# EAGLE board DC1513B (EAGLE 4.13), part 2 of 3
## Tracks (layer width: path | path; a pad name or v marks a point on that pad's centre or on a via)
3V  (via drill 0.3, 0.38)
  Top 0.152: v41.28,31.12 U9.G13
  Top 0.203: R29.2 81.92,12 v81.92,12.95
  Top 0.254: SJ2.1 U6.9 | SJ2.1 | U6.10 SJ1.1 79.12,64.14 | SJ2.1 79.63,64.13 79.63,64.14 | 79.38,65.53 79.5,65.53
  Top 0.305: 79.63,64.14 79.63,65.41 79.5,65.53 | 79.12,64.14 79.12,65.15 79.5,65.53 | 79.5,65.53 C15.1 | v41.91,27.31 U9.D14
  Top 0.406: v41.91,33.66 U9.J14
  Top 0.61: 79.38,65.53 79.38,65.41 78.99,65.02 77.47,65.02 77.09,64.64 v76.96,64.64 69.85,64.64 68.58,65.91 TP5.1 | U9.F13 v41.28,31.12 U9.G13
  L2-GND 0.203: 42.29,69.47 42.28,69.47 J4.2
  L2-GND 0.305: J3.6 35.59,65.31 36.07,65.79 36.07,69.98 36.45,70.36 42.29,70.36 | 42.28,69.34 42.29,69.34 42.29,69.47 42.29,70.36 | 42.29,70.36 54.99,70.36 56.13,69.22 66.04,69.22 TP5.1
  Bottom 0.203: v41.91,27.31 42.16,27.31 42.29,27.43 42.8,27.43 R28.2 | 42.67,37.08 R27.2 | R34.1 40.76,35.55 40.77,35.56
  Bottom 0.254: R36.1 41.72,70.36 41.78,70.36 42.28,69.87 J4.2 | R39.1 41.1,29.48 41.1,30.18 | v41.28,31.12 41.28,30.35 41.1,30.18 | R33.1 40.27,30.18 41.1,30.18
  Bottom 0.305: 81.15,13.59 v81.92,12.95 | J3.6 34.67,65.28 32.69,65.28 J3.5 | v41.91,27.31 41.28,27.94 41.28,28.96 41.02,29.21 41.02,29.46 R39.1
  Bottom 0.406: 81.15,13.59 79.88,13.59 78.74,14.73 78.74,44.96 77.72,45.97 77.72,58.55 76.96,59.31 v76.96,64.64 | L1.2 42.68,37.08 42.67,37.08 42.67,35.56 | 42.67,35.56 42.67,34.42 v41.91,33.66 41.4,33.15 41.4,32 41.28,31.88 v41.28,31.12 C20.1 | 42.67,35.56 40.77,35.56
  Bottom 0.508: L1.2 43.32,38.47 42.8,38.99 42.8,39.12 | 42.8,39.12 42.8,40.51 | 42.8,39.12 R32.2
  Bottom 0.61: TP5.1 68.58,69.03 C19.1 68.58,68.33 68.58,55.5 67.56,54.48 51.82,54.48 50.55,53.21 50.55,41.91 49.78,41.15 43.43,41.15 42.8,40.51
5V  (via drill 0.3)
  Top 0.305: U9.K5 v31.75,36.2 v34.29,36.2 U9.K8
  Top 0.406: v34.29,26.04 U9.C8 | U9.C5 v31.75,26.04 | v31.75,32.39 U9.G5 | v27.94,32.39 U9.H2
  Bottom 0.305: v34.29,36.2 31.88,36.2 | J8.1 25.04,69.34 J5.1 J5.2 | J5.2 27.18,69.31 27.18,69.34 27.15,69.31 J5.2 | J5.2 27.05,69.33 27.05,71.88 27.69,72.52 54.61,72.52 55.37,71.76 TP7.1 58.55,71.76 | C25.1 35.18,35.22 35.18,35.43
  Bottom 0.406: 31.88,36.2 v31.75,36.2 U9.K5 31.12,33.53 30.86,33.27 | v31.75,26.04 v34.29,26.04 | 30.86,33.27 30.61,33.02 28.58,33.02 v27.94,32.39 | 30.86,33.27 v31.75,32.39
  Bottom 0.508: 35.18,36.2 35.18,35.43 35.18,26.92 v34.29,26.04 | 35.18,36.2 v34.29,36.2 | 35.18,36.2 35.18,38.74 35.56,39.12 R31.2 36.97,40.02 37.21,40.26 41.4,40.26
  Bottom 0.61: TP7.1 58.42,68.96 C14.1 58.55,68.58 58.55,67.31 59.06,66.8 59.06,56.13 58.29,55.37 51.44,55.37 49.53,53.47 49.53,42.55 49.02,42.04 43.18,42.04 41.4,40.26
  other vias: 31.12,35.56
ADC_OEI  (via drill 0.25)
  Top 0.203: v40.64,27.31 U9.C13
  Bottom 0.203: v40.64,27.31 41.34,26.61 R12.2 R28.1 42.8,26.54
ADC_OEQ  (via drill 0.25)
  Top 0.203: U9.K13 v40.64,36.2
  Bottom 0.203: v40.64,36.2 40.96,36.52 R27.1 40.96,37.02 41.02,36.96 R27.1
AMP1I_EN  (via drill 0.25)
  Top 0.203: U9.D5 v30.48,28.58 | v33.66,43.05 37.08,43.05 38.74,44.7 38.74,62.87 38.61,62.99 26.54,62.99 26.04,63.5 26.04,67.06 25.78,67.31 J5.3 25.02,67.31
  L2-GND 0.203: v30.48,28.58 33.15,28.58 33.66,29.08 v33.66,43.05
  Bottom 0.203: v33.66,43.05 R11.1
AMP1Q_EN
  Top 0.203: U9.L5 31.75,37.47 31.75,41.91 32.39,42.55 35.69,42.55 | 35.69,42.55 37.08,42.55 39.12,44.58 39.12,63.12 38.86,63.37 28.58,63.37 28.07,63.88 28.07,67.06 27.81,67.31 J5.4 26.92,67.31 | 35.69,42.55 R8.1
AMP2I_EN  (via drill 0.25)
  Top 0.203: U9.C10 v38.1,27.31
  L2-GND 0.203: v38.1,27.31 37.47,27.94 v37.47,42.04
  Bottom 0.203: 37.47,43.18 R9.1 37.47,43.05 | v37.47,42.04 37.47,43.05 | 37.47,43.05 R11.2
AMP2Q_EN
  Top 0.152: U9.L10 38.1,37.47 38.1,41.15 37.85,41.4 35.94,41.4
  Top 0.203: 35.94,41.4 R8.2 34.99,41.59 34.8,41.4 R5.1
CLKIN
  Bottom 0.254: J7.1 51.38,3.05 | C2.1 49.15,29.08 49.21,29.14 R13.2
  Bottom 0.406: R13.2 50.17,29.16 51.61,29.16 53.59,27.18 53.59,21.97 51.44,19.81 J7.1
CLKINBUF  (via drill 0.25)
  Top 0.152: U9.F14 v43.18,31.12 U9.G14
  Bottom 0.254: U2.4 44.7,30.47 44.58,30.35 43.82,30.35 | 43.82,30.23 R10.1 43.82,30.35 | U8.2 44.58,33.66 43.82,32.89 43.82,31.12 | 43.82,31.12 43.82,30.35 | v43.18,31.12 43.82,31.12
CLKOUT
  Top 0.152: U5.3 72.88,28.32 72.9,28.32 72.77,28.45 69.47,28.45 68.2,29.72 49.28,29.72 47.88,31.12 45.97,31.12 45.72,30.86 45.72,30.23 45.34,29.85 40.64,29.85 U9.E12
DA0
  Top 0.152: U4.10 72.77,33.05 72.77,33.02 49.4,33.02 48.13,31.75 U9.G17
DA1
  Top 0.152: U4.9 72.88,33.4 72.9,33.4 72.77,33.53 49.15,33.53 48.01,32.39 45.72,32.39 U9.H16
DA2
  Top 0.152: U4.8 72.9,34.04 49.02,34.04 48.01,33.02 46.61,33.02 46.48,32.89 U9.H17
DA3
  Top 0.152: U4.7 73.03,34.55 73.03,34.54 48.9,34.54 48.01,33.66 45.72,33.66 U9.J16
DA4  (via drill 0.25)
  Top 0.152: U4.6 72.9,35.05 49.28,35.05 v48.64,35.69 | U9.L15 44.45,37.47 44.45,38.74 44.7,38.99 v48.51,38.99
  L2-GND 0.152: v48.51,38.99 48.51,38.35 48.64,38.23 v48.64,35.69
DA5  (via drill 0.25)
  Top 0.152: U4.5 72.9,35.55 72.9,35.56 49.4,35.56 49.15,35.81 v49.15,36.2 | U9.M15 43.82,38.74 44.58,39.5 48.9,39.5 49.15,39.24 v49.15,38.61
  L2-GND 0.152: v49.15,38.61 v49.15,36.2
DA6  (via drill 0.25)
  Top 0.152: U4.4 73.03,36.05 73.03,36.07 v49.91,36.07 | U9.M14 42.55,38.99 43.43,39.88 48.39,39.88 48.51,40.01 49.4,40.01 49.78,39.62 v49.78,38.99
  L2-GND 0.152: v49.78,38.99 49.78,36.32 49.91,36.2 v49.91,36.07
DA7
  Top 0.152: U4.3 72.9,36.55 | U4.3 | U4.3 51.33,36.55 50.42,37.47 45.85,37.47 U9.L16
DA8  (via drill 0.25)
  Top 0.152: U3.10 72.77,40.92 72.64,41.02 72.52,40.89 70.49,40.89 67.56,37.97 v50.8,37.97 | U9.L14 41.91,37.47 41.91,39.37 43.43,40.89 49.91,40.89 v50.67,40.13
  L2-GND 0.152: v50.67,40.13 51.05,39.75 51.05,38.23 v50.8,37.97
DA9  (via drill 0.25)
  Top 0.152: U9.K16 45.72,34.93 47.24,34.93 48.01,35.69 v48.01,36.07 | U3.9 70.51,41.42 67.56,38.48 52.2,38.48 52.07,38.35 51.44,38.35 51.31,38.48 50.55,38.48 50.17,38.1 v48.01,38.1
  L2-GND 0.152: v48.01,36.07 v48.01,38.1
DA10  (via drill 0.25)
  Top 0.152: U3.8 72.9,41.91 70.49,41.91 67.44,38.86 v51.69,38.86 | U9.M13 41.28,39.24 43.31,41.28 50.67,41.28 v51.69,40.26
  L2-GND 0.152: v51.69,40.26 v51.69,38.86
DA11  (via drill 0.25)
  Top 0.152: U3.7 72.9,42.42 70.49,42.42 67.31,39.24 52.2,39.24 52.07,39.37 51.31,39.37 51.18,39.24 50.8,39.24 v50.55,38.99 | U9.K15 44.45,36.2 47.24,36.2 47.75,36.7 v50.29,36.7
  L2-GND 0.152: v50.29,36.7 50.29,38.48 50.55,38.74 v50.55,38.99
DA12  (via drill 0.25)
  Top 0.152: U3.6 72.9,42.93 70.49,42.93 67.18,39.62 52.32,39.62 52.2,39.75 51.18,39.75 51.05,39.62 50.42,39.62 49.66,40.39 v43.69,40.39 | U9.K14 43.18,36.2 43.18,38.86 v43.69,39.37
  L2-GND 0.152: v43.69,39.37 v43.69,40.39
DA13
  Top 0.152: U3.5 72.77,43.42 72.77,43.43 70.49,43.43 67.06,40.01 52.71,40.01 51.05,41.66 43.05,41.66 40.64,39.24 40.64,37.47 U9.L13
DB0
  Top 0.152: U9.B13 40.64,24.77 40.64,22.23 41.91,20.96 46.99,20.96 47.24,20.7 51.18,20.7 51.69,21.21 51.69,22.48 52.07,22.86 63.5,22.86 69.57,16.79 U7.10
DB1
  Top 0.152: U9.C14 41.91,26.04 41.91,22.35 42.55,21.72 47.37,21.72 47.63,21.46 50.29,21.46 50.8,21.97 50.8,23.11 51.05,23.37 63.75,23.37 69.83,17.29 U7.9
DB2  (via drill 0.25)
  Top 0.152: U7.8 70.09,17.79 64.01,23.88 50.93,23.88 50.8,24 50.17,24 49.91,23.75 48.51,23.75 48.39,23.88 v47.88,23.88 | U9.C15 44.45,27.31 v48.01,27.31
  L2-GND 0.152: v48.01,27.31 48.01,26.8 47.75,26.42 47.75,25.15 47.63,25.02 47.63,24.51 47.75,24.38 47.75,24 v47.88,23.88
DB3  (via drill 0.25)
  Top 0.152: U7.7 70.35,18.29 64.26,24.38 v51.31,24.38 | U9.A13 41.28,22.23 42.16,21.34 47.12,21.34 47.37,21.08 50.8,21.08 51.31,21.59 v51.31,22.86
  L2-GND 0.152: v51.31,22.86 v51.31,24.38
DB4  (via drill 0.25)
  Top 0.152: U9.B14 43.18,24.77 43.18,22.86 43.56,22.48 47.88,22.48 48.13,22.23 49.53,22.23 49.91,22.61 v49.91,22.73 | U7.6 70.62,18.79 64.52,24.89 v49.91,24.89
  L2-GND 0.152: v49.91,22.73 49.91,23.75 50.04,23.88 50.04,24.51 49.91,24.64 v49.91,24.89
DB5
  Top 0.152: U9.C16 45.72,26.04 47.37,26.04 48.01,25.4 64.77,25.4 70.88,19.29 U7.5
DB6  (via drill 0.25)
  Top 0.152: U7.4 71.14,19.79 65.02,25.91 v48.64,25.91 | U9.B15 44.45,24.77 44.45,23.5 44.7,23.24 v48.64,23.24
  L2-GND 0.152: v48.64,23.24 48.64,23.88 48.51,24 48.51,24.49 48.64,24.61 v48.64,25.91
DB7  (via drill 0.25)
  Top 0.152: U7.3 71.4,20.29 65.28,26.42 52.58,26.42 52.45,26.29 50.8,26.29 50.67,26.42 v49.4,26.42 | U9.A15 43.82,23.24 44.2,22.86 48.13,22.86 48.39,22.61 49.15,22.61 49.4,22.86 v49.4,23.24
  L2-GND 0.152: v49.4,23.24 49.4,23.75 49.66,24 49.66,24.38 49.4,24.64 v49.4,26.42
DB8  (via drill 0.25)
  Top 0.152: U5.10 68.93,24.92 66.68,27.18 52.58,27.18 52.45,27.31 50.93,27.31 50.8,27.18 v50.42,27.18 | U9.A14 42.55,22.48 42.93,22.1 47.63,22.1 47.88,21.84 50.04,21.84 50.42,22.23 v50.42,23.5
  L2-GND 0.152: v50.42,23.5 v50.42,27.18
DB9  (via drill 0.25)
  Top 0.152: U5.9 69.2,25.42 66.93,27.69 49.66,27.69 v49.15,27.18 | U9.B16 45.72,24.77 v48.13,24.77
  L2-GND 0.152: v48.13,24.77 48.13,26.42 48.9,27.18 v49.15,27.18
DB10
  Top 0.152: U5.8 72.9,25.92 72.9,25.91 69.34,25.91 67.06,28.19 47.63,28.19 47.24,28.58 45.72,28.58 U9.D16
DB11  (via drill 0.25)
  Top 0.152: U5.7 72.9,26.42 69.47,26.42 67.31,28.58 48.51,28.58 48.39,28.7 v47.88,28.7 | U9.E16 45.34,29.21 45.34,29.34 45.47,29.34 45.97,29.85 v47.88,29.85
  L2-GND 0.152: v47.88,29.85 v47.88,28.7
DB12
  Top 0.152: U5.6 73.03,26.92 69.6,26.92 67.56,28.96 48.77,28.96 48.51,29.21 46.61,29.21 46.48,29.34 U9.E17
DB13
  Top 0.152: U5.5 72.9,27.43 69.72,27.43 67.82,29.34 49.15,29.34 48.01,30.48 46.48,30.48 46.36,30.61 U9.F17
GND  (via drill 0.25, 0.25 pad 0.25, 0.3, 0.38, 4.78)
  Top 0.152: 4.95,60.96 C4.2
  Top 0.203: 90.9,38.74 J1.24 | R23.1 82.55,62.68 v82.55,63.5 81.85,63.5 R30.1 | v76.2,63.63 76.19,62.68 | R19.1 76.9,63.56 | 76.19,62.68 R22.1 | 76.19,62.68 76.39,62.68 76.45,62.61 76.58,62.74 | Q1.2 82.93,9.71 82.93,9.65 83.37,9.21 R24.1 | R24.1 | R24.1 v84.2,10.03 | U5.4 72.03,27.92 v72.01,27.94 | U7.12 74.42,17.53 74.93,17.53
  Top 0.254: 89.74,26.77 J1.54 | v88.9,26.77 89,26.77 | 89.74,31.55 J1.42 | v88.95,31.55 89.08,31.55 | 89.63,29.15 89.69,29.13 J1.48 | v88.9,29.13 89.01,29.15 | 89.85,21.17 J1.60 | 89.79,18.72 J1.66 | v88.95,6.76 88.96,6.77 | C30.2 76.45,30.23 v76.45,29.34 | v72.14,30.23 C36.2 | C28.2 76.42,46.19 76.33,46.1 v76.33,45.34 | 73.15,46.23 C34.2 v72.14,46.23 | C29.2 76.42,37.63 v76.45,37.59 | U3.12 74.43,42.42 U3.GP | U3.11 73.93,41.92 U3.GP | U3.13 74.93,42.42 U3.GP | U4.12 74.43,34.55 U4.GP | U4.13 74.93,34.55 U4.GP | U4.11 73.93,34.05 U4.GP | U5.13 74.93,26.42 U5.GP | U5.11 73.93,25.92 U5.GP | U5.12 74.43,26.42 U5.GP | 79.25,61.09 U6.GP 79.63,60.71 U6.4 | v72.14,22.1 73.03,22.1 | v76.45,21.21 76.45,22.1 | U7.13 74.93,17.28 v74.68,17.53 | v74.68,17.53 74.42,17.53 | v74.68,17.53 73.91,17.53 73.91,16.13 | v74.68,17.53 74.93,17.53 | U3.3 71.91,44.42 71.88,44.45 71.88,43.92 74.45,43.92 v74.68,43.69 | 8.89,4.32 v8.26,5.08 | 8.89,70.61 5.08,70.61 v4.57,71.12 | 76.9,63.56 76.83,63.63 v76.2,63.63 | v33.02,41.4 33.91,41.4
  Top 0.305: 69.85,4.32 arc-90 71.63,2.54 arc-90 69.85,0.76 arc-90 68.07,2.54 arc-90 69.85,4.32 | 69.85,4.32 v68.58,5.08 | 4.83,60.96 4.95,60.96 6.99,60.96 TP2.1 6.99,59.69 C1.2 4.7,59.69 | v4.57,71.12 4.57,67.95 3.94,67.31 v1.27,67.31 | U9.D6 v36.83,27.94 U9.D11 U9.C11 U9.B11 | U9.L11 v39.37,37.47 | 39.88,37.08 U9.L12 | v36.83,37.47 U9.L9 | v26.67,24.13 26.16,24.13 25.27,25.02 | v25.4,24.13 25.4,24.26 25.53,24.38 | v26.67,27.94 26.16,27.94 25.15,26.92 | v27.31,37.47 v26.67,38.1 26.16,38.1 25.15,37.08 | v25.4,38.1 25.4,37.85 25.53,37.72 | v27.31,34.93 v26.67,34.29 U9.J1 25.27,35.05 | U9.H15 43.69,33.15 43.56,33.15 | v43.69,33.66 43.82,33.53 43.82,31.5 43.94,31.37 43.94,30.86 43.69,30.61 | v45.09,31.12 44.96,31.12 44.7,30.86 | v39.24,32.13 38.86,32.51 | v39.24,30.1 38.86,29.72 | 7.11,2.54 arc-90 8.89,4.32 arc-90 10.67,2.54 arc-90 8.89,0.76 arc-90 7.11,2.54 | 7.11,72.39 arc-90 8.89,74.17 arc-90 10.67,72.39 arc-90 8.89,70.61 arc-90 7.11,72.39
  Top 0.406: 89,26.77 89.74,26.77 | 89.08,31.55 89.74,31.55 | 89.01,29.15 89.63,29.15 | v88.9,21.18 89.85,21.17 | v88.88,18.77 89.79,18.72 | 88.96,6.77 J1.96 | J1.30 90.89,36.32 v88.9,36.32 | J1.36 90.87,33.91 v88.9,33.91 | J1.72 90.91,16.38 v88.9,16.38 | J1.78 v88.9,13.97 | J1.84 90.92,11.56 89.03,11.56 | J1.90 90.91,9.14 v88.9,9.14 | J1.6 v88.9,45.97 | v88.9,38.74 90.9,38.74 | J1.18 90.91,41.15 v88.9,41.15 | J1.12 v88.9,43.56 | C15.2 81.34,65.85 arc90 81.28,65.91 v82.55,65.91 | v82.55,65.15 81.41,65.15 81.41,65.66 | v76.71,54.99 76.71,56.13 | C9.2 v78.74,54.99 | C8.2 v80.77,54.99 | v1.27,48.64 0.64,48.64 0.64,48.13 | 0.64,48.13 0.64,45.34 5.46,45.34 5.72,45.59 5.72,47.88 5.46,48.13 0.64,48.13 | v1.27,40.01 1.02,39.75 0.64,39.75 0.64,36.7 5.46,36.7 5.72,36.96 5.72,39.24 5.46,39.5 0.89,39.5 | 0.89,22.73 v1.4,23.24 | 0.89,22.73 0.64,22.73 0.64,19.94 5.46,19.94 5.53,20 5.72,20.19 5.72,22.35 5.33,22.73 0.89,22.73 | 0.89,14.1 v1.4,14.61 | 0.89,14.1 5.46,14.1 5.72,13.84 5.72,11.56 5.46,11.3 0.64,11.3 0.64,14.1 0.89,14.1 | U9.C17 v47.12,26.67 | U9.B17 v47.12,25.4 | v47.12,24.13 U9.A17 v45.72,24.13 U9.A16 | U9.D15 v43.82,28.58 U9.E15 | U9.F15 U9.F16 v45.09,31.12 U9.G16 U9.G15 | U9.K17 v46.99,35.56 | v43.18,33.02 U9.H15 v43.69,33.66 | U9.L17 v46.99,36.83 | v46.99,38.1 U9.M17 v45.72,38.1 U9.M16 | 43.56,33.15 43.18,33.53 43.18,33.27 43.56,32.89 42.67,32.89 42.42,33.15 42.8,33.15 | v33.02,36.83 33.4,37.21 33.4,38.1 | v36.83,37.47 36.7,37.34 35.05,37.34 35.05,37.72 36.58,37.72
  Top 0.61: 5.53,20 5.53,20.07 5.72,19.81 v5.97,19.56 | v26.67,31.75 v25.4,31.75 | v26.67,31.75 U9.G2 27.31,31.5 | v26.67,30.48 U9.F2 v27.31,31.12 v25.02,31.12 | v26.67,30.48 v25.4,30.48 v25.4,31.75 | v26.67,30.48 v26.67,31.75 | v26.04,29.85 26.04,30.35 26.04,32.26 v26.04,32.39 | v26.04,32.39 U9.H1 v25.4,33.02 v25.4,31.75 | v24.89,32.51 25.02,32.39 v26.04,32.39 | v29.85,38.74 v29.85,37.47 v29.85,34.93 v29.85,33.66 | v29.85,33.66 v29.85,32.39 29.85,32.26 v29.85,31.12 | v29.85,31.12 U9.F4 v29.21,30.48 | v29.21,30.48 v27.94,30.48 v26.67,30.48 | v29.85,31.12 28.7,31.12 | v29.21,30.48 v29.21,31.75 | U9.M16 v46.99,38.1 | U9.L17 v46.99,36.83 | U9.K17 v46.99,35.56 | v43.82,28.58 U9.E15 U9.E14 | U9.D15 v43.82,28.58 | v43.82,28.58 43.82,28.7 43.43,29.08 | U9.C17 v47.12,26.67 | U9.B17 v47.12,25.4 | v47.12,24.13 U9.A16 | v33.02,36.83 33.15,36.96 34.93,36.96 34.93,37.59 33.91,37.59 33.91,37.34 34.54,37.34 | 33.15,32.26 38.35,32.26 38.48,32.13 38.48,32.64 32.64,32.64 32.64,33.27 37.21,33.27 37.34,33.4 37.34,33.78 32.51,33.78 v32.39,33.66 31.12,33.66 | v36.83,27.94 36.83,28.32 32.64,28.32 32.64,28.83 32.77,28.7 37.21,28.7 | v38.1,29.21 38.35,28.96 38.61,28.96 38.61,28.19 37.85,28.19 37.85,28.7 37.97,28.58 38.35,28.58 | v38.1,25.4 37.97,25.27 37.59,25.27 37.47,25.15 33.66,25.15 | v38.74,24.77 38.86,24.89 38.86,25.27 40.01,25.27 | 32.39,25.27 32.26,25.15 31.12,25.15 | 26.8,38.1 27.05,37.85 27.05,34.54 25.53,34.54 | v27.31,37.47 26.92,37.85 25.65,37.85 | v27.31,27.31 26.92,27.69 25.4,27.69 | v27.31,24.77 26.92,24.38 25.65,24.38 | 26.8,24.13 27.05,24.38 27.05,27.69 | U9.G15 43.82,34.16 v43.69,33.66 | v43.18,33.02 42.8,33.02 43.82,34.04
  Top 0.61: v30.48,34.29 U9.J5 31.12,33.66 | 31.12,33.4 31.12,33.66 | 31.12,33.4 31.12,33.27 | 31.12,33.27 U9.H5 29.97,33.02 29.97,33.53 v29.85,33.66 | v29.85,33.66 30.99,33.66 30.99,33.53 31.12,33.4 | 31.12,33.4 30.23,33.4 30.1,33.27 | v33.02,33.02 U9.H6 32.13,33.27 31.12,33.27
  Top 0.635: v29.21,31.75 U9.G3 v28.58,29.85 | v28.58,28.58 v28.58,29.85 | v28.58,28.58 v28.58,23.5 | U9.A4 v29.85,23.5 | v29.85,24.77 U9.A4 | U9.B4 v29.85,24.77 | v29.85,26.04 U9.B4 | v29.85,26.04 U9.D4 v29.21,27.94 | v27.94,27.94 v29.21,27.94 | U9.D2 v27.94,27.94 | U9.D2 v26.67,27.94 | v26.67,27.94 25.65,27.94 | 25.65,27.94 v25.4,27.94 | v27.94,27.94 v27.94,24.13 | v27.94,24.13 27.94,23.5 | v27.31,24.77 v27.31,23.5 v26.04,23.5 | v27.31,24.77 v27.31,27.31 | v27.31,27.31 U9.D2 | v26.67,24.13 v25.4,24.13 25.91,23.62 | v26.67,24.13 26.8,24.13 v27.94,24.13 | v29.21,38.1 v29.21,39.37 | v29.21,34.29 v29.21,38.1 | U9.J3 v28.58,38.74 | v27.94,34.29 27.94,38.74 | U9.M2 v27.31,38.74 | U9.M2 v27.31,37.47 v27.31,34.93 U9.J2 | v25.4,34.29 v26.67,34.29 v29.21,34.29 | v29.21,34.29 v30.48,34.29 | v30.48,34.29 U9.J5 v31.75,34.29 | v31.75,34.29 v33.02,34.29 | v33.02,34.29 v34.29,34.29 | v34.29,34.29 v36.83,34.29 | v36.83,34.29 v38.1,34.29 | v38.1,34.29 v38.1,35.56 | v38.1,34.29 v38.1,33.02 v33.02,33.02 U9.H6 | v38.1,31.75 v38.1,29.21 | v38.1,29.21 U9.E11 U9.H11 | v38.1,31.75 v34.29,31.75 U9.G6 | v38.1,31.75 U9.G12 40.01,31.12 | 40.01,31.12 U9.F12 37.34,30.48 | 37.34,30.48 U9.F6 | U9.F6 31.62,30.48 | 31.62,30.48 U9.F5 | v32.39,31.12 40.01,31.12 | v38.1,31.75 U9.E10 U9.J10 | 32.89,32.39 32.64,32.64 32.39,32.89 v32.39,33.66 v32.39,34.93 | 32.89,32.39 33.02,32.26 | 32.89,32.39 32.64,32.39 32.64,32 arc-90 U9.G6 | v32.39,31.12 U9.G6 | U9.F6 v32.39,31.12 | U9.H4 v29.85,33.66 v29.21,34.29 | v32.39,34.93 U9.K6 v33.02,35.56 | v33.02,35.56 U9.K7 U9.J7 v33.02,34.29 | v33.02,34.29 v33.02,35.56 | U9.L7 v33.02,36.83 | U9.L8 U9.L9 v36.83,37.47 | v36.83,38.1 v36.83,37.47 | v36.83,38.1 36.83,38.61 32.39,38.61 U9.L6 v33.02,36.83
  Top 0.635: v33.02,36.83 v33.02,38.1 33.4,38.1 v36.83,38.1 | v36.83,38.1 v36.83,37.47 | v36.83,38.1 U9.M10 37.47,38.48 37.21,38.74 | 38.86,37.08 38.86,38.74 | 38.86,37.08 38.74,37.08 | 39.88,37.08 39.5,37.47 v39.37,37.47 39.88,37.08 | 39.88,37.08 40.01,36.96 40.01,38.74 39.75,38.99 | v38.1,29.21 v31.75,29.21 31.62,29.21 | 31.62,29.21 U9.E5 | U9.D7 v33.02,27.94 | U9.D7 v36.83,27.94 37.34,27.94 37.34,30.48 | v38.1,29.21 38.1,29.72 37.97,29.85 32.13,29.85 31.62,30.35 31.62,29.21 | 32.39,28.96 U9.C6 U9.C7 U9.D7 | U9.D7 32.77,27.94 32.77,27.81 33.02,27.56 33.02,27.05 | v40.01,23.5 U9.A12 U9.A4 | U9.A4 v29.85,23.5 | v29.85,23.5 v40.01,23.5 | v40.01,23.5 v40.01,24.77 | v37.47,24.77 v38.74,24.77 v40.01,24.77 | 36.07,24.77 v37.47,24.77 | v33.66,24.77 36.07,24.77 | v32.39,24.77 v33.66,24.77 | v29.85,24.77 v32.39,24.77 | U9.B4 v29.85,24.77 | U9.B4 v30.48,25.4 | v30.48,25.4 U9.B5 31.12,25.15 31.12,24.89 | v32.39,24.77 32.39,25.27 U9.B6 U9.B7 33.66,25.15 v33.66,24.77 | 34.93,24.89 U9.B8 U9.B9 36.2,24.89 36.07,24.77 | v37.47,24.77 U9.B10 v38.1,25.4 U9.B11 38.74,24.89 | v40.01,24.77 40.01,25.27 U9.B12 | 39.88,37.08 38.86,37.08 | v29.85,38.74 30.99,38.74 30.99,38.1 v30.48,38.1 | v29.21,38.1 v30.48,38.1 | v25.4,38.1 v26.67,38.1 26.8,38.1 U9.M2 | U9.M2 v27.31,38.74 | v27.31,38.74 25.27,38.74 | 29.85,32.26 29.08,31.5 27.31,31.5 v27.31,31.12 27.81,31.12 | v26.67,31.75 26.54,31.75 26.04,32.26 | v25.4,29.21 25.4,30.35 26.04,30.35 U9.E1 v25.4,29.21 | v26.67,30.48 v25.4,29.21 | v28.58,29.85 v27.94,30.48 27.94,30.99 27.81,31.12 | v27.94,27.94 v28.58,28.58 | 27.81,31.12 28.7,31.12 | v27.31,24.77 v26.67,24.13 | v27.31,27.31 v26.67,27.94 | v25.02,27.18 25.02,27.31 25.4,27.69 25.65,27.94
  Top 0.635: v29.85,26.04 v30.48,25.4 | v29.21,27.94 v28.58,28.58 | v28.58,29.85 v29.21,30.48 | 31.62,30.48 v31.75,30.48 v32.39,31.12 | v29.85,32.39 29.85,32.51 | v29.85,34.93 v30.48,34.29 | v31.75,34.29 v32.39,34.93 | v29.85,37.47 v30.48,38.1 | v34.29,34.29 33.78,34.8 | v36.83,34.29 37.47,34.93 U9.K10 U9.K11 U9.J11 v38.1,34.29 | v38.1,34.29 37.72,34.67 | v38.1,34.29 38.35,34.29 38.48,34.16 38.48,33.15 | v36.83,37.47 37.34,37.97 | v45.09,31.12 U9.G16 U9.G15 | v45.09,31.12 U9.F16 U9.F15 | v45.09,31.12 44.83,31.12 44.32,31.62 44.32,30.73 | U9.J15 43.82,34.04 v43.69,33.66 U9.H15
  Top 0.711: v29.21,27.94 29.21,23.5
  Top 0.813: v39.37,37.47 39.37,38.86
  Bottom 0.152: v4.45,3.81 7.11,2.54
  Bottom 0.203: J1.54 | 90.87,29.16 J1.48 | J1.42 90.8,31.37 88.9,31.37 v88.95,31.55 | 90.85,33.96 J1.36 | v88.95,31.55 arc90 88.9,31.37 v88.95,31.55 | 88.86,32.17 88.85,32.18 | J1.96 88.78,6.77 v88.95,6.76 | 89.03,11.56 87.88,11.56
  Bottom 0.254: 89.15,47.57 88.9,47.32 88.9,46.61 88.93,46.61 89.08,46.77 | 80.65,2.29 80.65,4.19 | v74.68,33.78 74.68,32.42 | v6.35,0.76 7.09,0.53 9.5,0.53 | v72.39,1.27 71.65,0.53 69.22,0.53 | v10.8,73.66 10.06,74.4 8.05,74.4 | SJ4.1 42.8,28.58 v43.82,28.58 | 42.29,65.28 42.29,64.9 41.78,64.39 41.78,64.26 41.66,64.14 R42.1 | 37.47,43.94 v37.47,44.96
  Bottom 0.305: J7.5 47.12,4.24 | 7.11,72.39 arc-90 8.89,74.17 arc-90 10.67,72.39 arc-90 8.89,70.61 arc-90 7.11,72.39 | 68.07,2.54 arc90 69.85,0.76 arc90 71.63,2.54 arc90 69.85,4.32 arc90 68.07,2.54 | 67.31,2.54 68.07,2.54 | 7.11,72.39 5.84,71.12 v4.57,71.12 | U8.3 44.47,34.31 44.45,34.29 | 42.29,65.28 43.69,65.28 | v48.64,27.69 48.64,27.81 48.77,27.94 | v48.64,27.69 48.77,27.69 49.02,27.94 | v48.64,27.69 48.39,27.94 | 8.89,4.32 arc-90 10.67,2.54 arc-90 8.89,0.76 arc-90 7.11,2.54 arc-90 8.89,4.32
  Bottom 0.406: J1.84 90.92,11.56 89.03,11.56 | J1.12 | J1.90 88.92,9.17 v88.9,9.14 | J1.84 88.91,11.57 88.9,11.56 v88.98,11.56 | J1.84 90.93,11.56 89.03,11.56 | 91.06,41.15 91.04,41.17 | J1.12 | J1.6 | J1.6 | J1.12 v88.9,43.56 | J1.18 90.91,41.15 v88.9,41.15 | J1.24 90.9,38.74 v88.9,38.74 | J1.6 v88.9,45.97 88.9,46.61 | v48.97,1.27 48.97,0.64 48.46,0.64 | 48.46,0.64 45.67,0.64 45.67,5.46 45.92,5.72 48.08,5.72 48.46,5.33 48.46,0.64 | v54.05,1.27 54.05,0.64 54.31,0.64 | 54.31,0.64 57.1,0.64 57.1,5.46 56.85,5.72 54.56,5.72 54.31,5.46 54.31,0.64 | 89.03,11.56 89.03,11.48 87.25,11.48 | v43.69,33.66 44.2,34.29 44.45,34.29 | v50.17,30.86 50.17,30.1
  Bottom 0.508: v88.9,26.77 J1.54 | 89.03,29.16 90.87,29.16 | 89.1,33.96 90.85,33.96 | J1.42 89,31.57 | 88.88,21.17 J1.60 | J1.66 89.79,18.75 v88.88,18.77 | J1.84 89.95,11.57 | v88.98,11.56 89.03,11.56 89.94,11.56 | 89.15,47.57 J1.2 | 89.08,46.77 J1.4
  Bottom 0.61: v88.9,29.13 89.03,29.16 | v88.9,33.91 89.1,33.96 | v88.9,21.18 88.88,21.17 | 89.94,11.56 89.95,11.57 | 47.07,3.05 47.07,4.32 | 73.74,71.83 TP4.1 73.61,71.7
  Bottom 0.711: v9.4,43.82 6.99,43.82 6.48,44.32 | v9.27,41.02 7.11,41.02 6.73,40.64 | v7.87,18.42 7.11,18.42 6.73,18.8 | v7.87,15.62 7.11,15.62 6.86,15.37
  other vias: 48.97,5.08 44.53,1.52 48.97,3.81 48.97,2.54 58.5,0.76 54.05,2.54 54.05,3.81 48.97,6.1 45.42,2.54 44.53,0.76 45.42,3.81 45.42,5.08 45.42,6.1 46.43,6.1 47.07,6.1 47.7,6.1 58.5,1.52 55.32,6.1 55.96,6.1 56.59,6.1 57.61,5.08 58.5,2.41 57.61,3.81 57.61,2.54 4.57,23.24 4.57,18.8 3.3,18.8 2.03,18.8 6.35,21.34 6.35,22.1 6.1,22.99 2.03,23.24 2.67,23.24 3.3,23.24 3.94,23.24 5.21,23.24 1.4,10.8 2.03,10.8 2.67,10.8 3.3,10.8 3.94,10.8 4.57,10.8 5.21,10.8 6.1,11.05 6.35,11.94 6.35,12.7 5.84,15.24 6.35,13.59 4.57,15.24 3.3,15.24 2.03,15.24 6.35,20.45 5.21,19.43 3.94,19.43 2.67,19.43 1.4,19.43 5.21,14.61 3.94,14.61 2.67,14.61 85.98,23.83 85.98,25.6 74.93,3.81 4.45,48.64 4.45,44.2 3.18,44.2 1.91,44.2 6.22,46.74 6.22,47.5 5.97,48.39 1.91,48.64 2.54,48.64 3.18,48.64 3.81,48.64 5.08,48.64 1.27,36.2 1.91,36.2 2.54,36.2 3.18,36.2 3.81,36.2 4.45,36.2 5.08,36.2 5.84,36.32 6.22,37.34 6.22,38.1 5.97,39.88 5.59,40.64 6.22,38.99 4.45,40.64 3.18,40.64 1.91,40.64 6.22,45.85 5.97,45.09 3.81,44.83 2.54,44.83 1.27,44.83 5.08,40.01 3.81,40.01 2.54,40.01 54.05,5.08 57.61,1.27 54.05,6.1 57.61,6.1 45.42,1.27 85.22,29.26 87.25,29.26 87.25,43.56 87.38,45.97 87.12,26.9 85.34,26.9 66.04,0.76 66.04,5.08 0.76,5.08 1.27,57.15 1.27,62.23 26.67,73.66 31.75,73.66 36.83,73.66 41.91,73.66 46.99,73.66 80.01,73.66 85.09,68.58 85.47,64.77 85.34,59.69 85.09,49.53 82.55,52.07 85.47,62.23 85.47,66.68 73.03,50.17 1.27,54.61 1.27,59.69 1.27,64.77 0.76,3.18 66.04,2.54 78.87,7.24 63.5,0.76 66.04,7.62 63.5,2.54 63.5,5.08 63.5,7.62 82.17,71.12 70.74,39.5 74.68,26.67 74.68,27.69 74.68,25.65 74.68,35.81 74.68,34.8 74.68,41.66 74.68,42.67 80.01,61.47 80.01,60.45 79.38,60.96 80.65,60.96 78.11,60.96 78.74,61.47 78.74,60.45 84.07,39.62 83.57,38.61 87,38.74 85.09,38.74 86.36,41.28 84.71,36.32 86.61,36.45 85.73,33.91 87.12,33.91 85.85,31.62 87.5,31.62 83.44,30.86 77.98,31.75 84.33,30.1 83.57,29.08 77.98,37.85 77.98,39.62 85.09,52.07 78.74,46.36 78.74,49.53 80.01,52.07 83.19,54.61 72.14,29.21 76.07,13.84 70.49,46.36 70.74,44.32 85.47,45.97 74.68,19.56 74.68,18.54 72.26,23.88 72.26,15.75 72.26,14.73 77.98,23.44 77.98,21.67 76.45,23.44 81.03,12.95 81.79,13.84 68.71,37.34 70.74,37.34 69.85,38.48 69.85,37.34 70.74,38.48 4.95,44.83 70.61,23.5 70.61,24.26 71.37,24.26 71.37,23.5 69.85,30.99 69.85,30.1 69.85,29.21 69.22,30.51 69.67,32.39 70.71,32.39 0.76,29.72 0.69,32.51 0.69,26.92 5.97,14.61 6.48,14.22 87.6,18.77 88.77,22.71 87,21.18 86.11,22.07 87,22.83 85.6,43.56 6.22,50.04 5.33,50.04 4.45,50.04 3.56,50.04 2.67,50.04 1.78,50.04 0.89,50.04 6.1,34.8 5.21,34.8 4.32,34.8 3.43,34.8 2.54,34.8 1.65,34.8 0.76,34.8 6.6,24.51 5.72,24.51 4.83,24.51 3.94,24.51 3.05,24.51 2.29,24.51 0.76,24.51 1.52,24.51 6.73,9.53 5.84,9.53 4.95,9.53 4.06,9.53 3.18,9.53 2.29,9.53 1.52,9.53 0.76,9.53 58.5,3.3 58.5,4.19 58.5,5.08 58.5,5.97 58.37,6.73 57.48,6.99 56.59,6.99 55.7,6.99 54.81,6.99 44.53,2.41 44.53,3.3 44.53,4.19 44.53,5.08 44.53,5.97 44.65,6.73 45.54,6.99 46.56,6.99 47.57,6.99 48.46,6.99 73.15,10.92 73.79,9.27 74.04,8 75.06,7.49 77.85,7.24 76.45,7.11 70.49,45.21 71.76,57.79 74.04,59.31 54.74,73.79 22.23,73.66 73.91,55.88 67.31,55.88 54.61,56.26 60.96,55.88 57.79,56.26 57.79,52.71 57.79,50.17 60.96,52.71 64.14,52.71 67.31,52.71 70.49,52.71 70.49,50.17 67.31,50.17 64.14,50.17 60.96,50.17 67.31,46.99 70.49,46.99 60.96,46.99 57.79,46.99 64.14,46.99 3.81,54.61 8.89,54.61 6.35,54.61 8.89,57.15 6.35,55.88 3.81,67.31 41.28,12.7 38.74,12.7 36.2,12.7 41.28,10.16 43.82,10.16 46.36,10.16 48.9,10.16 38.74,10.16 36.2,10.16 33.66,10.16 31.12,10.16 33.66,12.7 31.12,12.7 43.82,20.32 28.58,10.16 23.5,7.62 10.8,7.62 8.26,7.62 5.72,7.62 3.18,7.62 0.76,7.62 10.8,5.08 23.5,5.08 23.5,2.54 23.5,0.76 26.04,7.62 26.04,5.08 26.04,2.54 26.04,0.76 28.58,7.62 28.58,5.08 28.58,2.54 28.58,0.76 31.12,7.62 31.12,5.08 31.12,2.54 31.12,0.76 33.66,7.62 36.2,7.62 38.74,7.62 41.28,7.62 43.82,7.62 41.28,5.08 43.82,5.08 43.82,2.54 43.82,0.76 41.28,2.54 41.28,0.76 38.74,0.76 38.74,2.54 38.74,5.08 36.2,5.08 36.2,2.54 36.2,0.76 33.66,5.08 33.66,2.54 33.66,0.76 10.8,0.76 10.8,2.54 55.88,10.16 55.88,7.62 58.42,10.16 58.42,7.62 60.96,7.62 60.96,5.08 60.96,2.54 60.96,0.76 63.5,10.16 60.96,10.16 66.04,10.16 68.58,12.7 68.58,10.16 68.58,7.62 71.12,7.62 71.12,10.16 71.12,12.7 71.12,5.08 78.74,6.35 78.74,3.81 78.74,1.27 46.36,17.78 80.65,2.79 80.01,4.95 28.58,34.93 28.58,36.2 27.94,35.56 27.31,36.2 28.58,37.47 27.94,38.1 27.94,36.83 29.85,36.2 28.58,31.12 26.04,31.12 26.04,38.74 28.58,27.31 27.94,26.67 29.21,26.67 28.58,26.04 27.31,26.04 27.94,25.4 29.21,25.4 29.21,24.13 28.58,24.77 27.94,31.12 27.94,34.93 39.37,38.74 26.67,31.12 27.94,27.31 32.39,38.1 29.85,27.31 30.48,24.13 31.75,24.13 33.02,24.13 34.29,24.13 35.56,24.13 36.83,24.13 38.1,24.13 39.37,24.13 36.2,24.77 34.93,24.77 31.12,24.77 31.12,23.5 32.39,23.5 33.66,23.5 34.93,23.5 36.2,23.5 37.47,23.5 38.74,23.5 38.1,30.48 33.02,31.75 33.02,30.48 32.39,29.85 36.83,33.02 36.83,31.75 36.83,30.48 36.83,29.21 35.56,25.4 33.66,27.31 32.39,27.31 34.29,29.21 34.29,27.94 34.29,30.48 34.29,33.02 34.29,38.1 29.21,36.83 29.21,35.56 39.37,38.1 32.39,27.94 73.03,52.71 51.56,56.26 54.61,52.71 54.61,50.17 54.61,46.99 51.56,46.99 51.56,50.17 51.56,52.71 54.61,58.17 51.56,58.17 57.79,58.17 67.31,43.82 64.14,43.82 60.96,43.82 57.79,43.82 54.61,43.82 51.56,43.82 54.61,40.77 57.79,40.77 60.96,40.77 64.14,40.77 67.31,41.28 46.61,50.55 44.7,43.69 48.26,45.72 46.48,44.32 48.26,48.9 43.18,44.07 45.09,48.9 48.9,55.25 46.36,58.42 41.91,58.42 41.91,55.25 45.09,52.07 48.26,52.07 36.83,54.74 36.83,57.15 36.83,52.07 36.83,49.53 29.21,46.99 26.67,46.99 34.29,44.45 26.8,44.45 27.69,43.43 29.21,44.45 46.36,15.24 28.58,17.78 28.58,15.24 28.45,12.7 26.04,15.24 26.04,17.78 43.82,15.24 43.82,12.7 46.36,12.7 43.82,17.78 51.44,42.16 42.67,42.8 47.37,42.93 53.09,37.21 57.79,37.21 54.61,37.21 60.83,37.21 64.14,37.21 50.17,32 52.71,30.48 54.61,32.26 51.82,32 56.52,30.48 60.33,30.48 58.42,32.26 64.14,30.48 62.23,32.26 67.95,30.48 66.04,32.39 66.42,26.42 68.45,24.38 58.42,12.7 55.88,12.7 53.34,12.7 53.34,10.16 53.34,7.62 60.96,12.7 63.5,12.7 66.04,12.7 53.34,15.24 55.88,15.24 58.42,15.24 60.96,15.24 63.5,15.24 66.04,15.24 68.58,15.24 71.12,15.24 66.04,17.78 63.5,17.78 60.96,17.78 58.42,17.78 55.88,17.78 53.34,17.78 55.88,20.45 58.42,20.32 60.96,20.32 63.5,20.32 60.96,22.1 63.25,22.1 58.42,22.1 55.88,22.1 49.02,24.26 51.18,26.8 52.2,26.8 44.45,26.04 32.39,24.13 31.12,24.13 40.64,26.04 11.43,54.61 13.97,54.61 16.51,54.61 19.05,54.61 21.59,54.61 24.13,54.61 26.67,54.61 29.21,54.61 31.75,54.61 1.27,52.07 3.81,52.07 6.35,52.07 8.89,52.07 11.43,52.07 13.97,52.07 16.51,52.07 19.05,52.07 21.59,52.07 24.13,52.07 26.67,52.07 29.21,52.07 31.75,52.07 31.75,49.53 29.21,49.53 26.67,49.53 24.13,49.53 21.59,49.53 19.05,49.53 16.51,49.53 13.97,49.53 11.43,49.53 8.89,49.53 8.89,46.99 11.43,46.99 13.97,46.99 16.51,46.99 19.05,46.99 21.59,46.99 24.13,46.99 24.13,44.45 21.59,44.45 19.05,44.45 16.51,44.45 13.97,44.45 11.43,44.45 8.89,44.45 7.87,40.89 24.13,41.91 21.59,41.91 19.05,41.91 26.67,41.91 29.21,41.91 26.67,39.37 24.38,39.24 21.59,39.37 19.05,39.37 20.32,38.1 22.86,38.1 16.38,41.91 16.76,40.13 14.73,42.04 18.8,38.1 21.59,38.1 17.65,39.24 15.75,41.15 13.84,43.05 12.57,43.82 10.92,43.82 7.75,43.94 10.54,41.02 11.94,41.02 12.7,40.13 13.59,39.37 14.35,38.48 15.24,37.59 23.88,31.75 24.64,31.75 22.86,32.64 23.11,31.88 23.88,30.48 24.77,29.59 24.64,30.35 22.99,29.59 23.11,30.35 24.26,31.12 23.37,31.12 24.89,24.64 24.26,24.26 24.77,23.75 22.73,27.05 21.46,27.05 20.45,27.05 19.18,27.05 17.91,27.05 23.5,24.13 22.48,24.13 21.46,24.13 20.32,24.13 19.18,24.13 18.29,23.75 17.53,22.99 16.76,22.23 16,21.46 15.24,20.7 14.48,19.94 13.72,19.18 12.95,18.42 12.19,17.65 11.43,16.89 10.67,16.13 9.91,15.62 8.89,15.62 15.62,25.02 14.86,24.26 14.1,23.5 13.21,22.61 12.45,21.84 11.56,20.96 10.67,20.07 9.78,19.18 9.02,18.42 7.87,19.3 7.87,20.32 7.87,21.46 7.87,22.61 7.87,23.75 7.37,24.26 7.75,14.73 7.75,13.72 7.75,12.7 7.75,11.68 7.75,10.67 7.24,10.03 16.89,27.05 15.62,27.05 14.35,27.05 13.21,27.05 11.94,27.05 10.67,27.05 14.22,25.02 12.95,25.02 11.81,25.02 10.54,25.02 22.73,35.18 21.59,35.18 20.32,35.18 19.05,35.18 17.78,35.18 16.51,35.18 14.61,37.21 15.24,35.18 13.97,35.18 12.7,35.18 11.43,35.18 13.34,37.21 12.07,37.21 10.8,37.21 9.53,37.21 8.26,37.21 11.43,39.37 9.53,39.37 7.75,39.37 10.41,38.35 8.64,38.35 12.83,38.35 7.62,35.56 8.89,36.2 9.27,25.02 8.38,24.64 12.07,23.5 10.16,23.5 8.89,22.23 10.8,22.23 9.53,20.96 8.89,19.69 8.89,23.5 9.4,27.05 10.41,34.67 9.65,33.66 9.65,32.39 9.65,31.12 8.89,30.23 8,29.46 7.62,28.58 7.62,27.56 8.38,27.05 22.23,31.12 20.96,31.12 19.69,31.12 18.42,31.12 17.15,31.12 15.88,31.12 14.61,31.12 13.34,31.12 12.07,31.12 10.8,31.12 11.43,32.39 12.7,32.39 13.97,32.39 15.24,32.39 16.51,32.39 17.78,32.39 19.05,32.39 20.32,32.39 21.59,32.39 21.59,29.85 20.32,29.85 19.05,29.85 17.78,29.85 16.51,29.85 15.24,29.85 13.97,29.85 12.7,29.85 11.43,29.85 10.16,29.85 20.96,28.58 22.23,28.58 19.69,28.58 18.42,28.58 17.15,28.58 15.88,28.58 14.61,28.58 13.34,28.58 12.07,28.58 10.8,28.58 9.53,28.58 8.51,28.58 22.23,33.66 20.96,33.66 19.69,33.66 18.42,33.66 17.15,33.66 15.88,33.66 14.61,33.66 13.34,33.66 12.07,33.66 10.8,33.66 10.54,32.39 22.86,40.64 20.32,40.64 18.16,40.64 33.66,15.24 36.2,15.24 38.74,15.24 41.28,15.24 31.12,15.24 33.66,17.78 36.2,17.78 38.74,17.78 41.28,17.78 31.12,17.78 31.12,20.32 33.66,20.32 36.2,20.32 38.74,20.32 41.28,20.32 38.74,22.86 36.2,22.86 33.66,22.86 31.12,22.86 28.58,20.32 28.58,22.86 26.04,20.32 26.04,22.86 23.5,20.32 23.5,22.86 20.96,22.86 20.96,20.32 18.42,22.86 23.5,17.78 20.96,17.78 23.5,15.24 20.96,15.24 18.42,15.24 15.88,15.24 13.34,15.24 13.34,17.78 15.88,17.78 17.65,20.96 17.65,17.27 15.88,19.18 19.56,19.18 26.04,10.16 23.5,10.16 26.04,12.7 23.5,12.7 20.96,12.7 18.42,12.7 15.88,12.7 13.34,12.7 10.8,12.7 10.8,15.24 20.96,10.16 18.42,10.16 15.88,10.16 13.34,10.16 10.8,10.16 20.96,7.62 18.42,7.62 15.88,7.62 13.34,7.62 20.96,5.08 18.42,5.08 15.88,5.08 13.34,5.08 20.96,2.54 18.42,2.54 15.88,2.54 13.34,2.54 20.96,0.76 18.42,0.76 15.88,0.76 13.34,0.76 46.36,7.62 48.9,7.62 48.9,12.7 48.9,15.24 48.9,17.78 49.02,19.94 50.04,18.92 50.04,16.51 50.04,13.84 50.04,11.43 50.04,8.89 52.83,8.76 52.83,11.3 52.83,13.97 52.83,16.64 52.96,19.18 50.04,19.94 54.61,20.96 54.99,22.1 51.82,31.12 50.93,32 31.75,57.15 29.21,57.15 26.67,57.15 24.13,57.15 21.59,57.15 19.05,57.15 16.51,57.15 13.97,57.15 11.43,57.15 11.43,59.31 13.97,59.31 16.51,59.31 19.05,59.31 21.59,59.31 24.13,59.31 26.67,59.31 29.21,59.31 31.75,59.31 11.43,61.6 15.24,68.33 12.95,68.33 15.24,64.77 13.59,64.77 13.72,62.74 17.65,62.74 19.43,63.12 21.21,65.02 20.83,68.33 22.73,68.33 22.99,66.04 6.35,67.31 6.35,64.77 8.26,69.22 1.27,73.66 17.78,73.66 13.34,73.66 10.67,70.74 14.35,70.23 21.97,70.23 29.34,69.98 38.1,69.47 48.9,66.04 33.78,71.63 38.99,71.63 44.7,71.63 56.52,68.45 56.52,63.5 43.18,63.5 46.36,63.5 51.44,63.5 51.44,68.58 46.36,68.58 43.82,68.58 38.48,65.02 36.45,65.02 36.83,67.56 37.85,67.56 28.83,67.56 31.24,67.56 31.24,65.15 28.83,65.02 31.75,46.99 31.75,44.45 30.48,43.18 25.4,40.64 27.94,40.64 10.16,45.72 12.7,45.72 15.24,45.72 15.24,43.69 8,45.72 24.77,37.72 24,37.97 24.51,38.48 25.15,38.86 23.75,38.74 35.56,40.64 36.7,41.91 34.93,40.01 32.64,40.26 39.37,41.66 39.37,43.31 45.85,42.93 43.69,42.93 79.76,29.21 81.92,29.21 79.63,31.62 82.68,31.62 81.03,31.62 80.14,30.35 81.92,30.35 79.63,36.83 81.79,36.83 79.63,39.62 81.79,39.62 80.52,38.23 82.17,38.23 77.98,43.82 79.76,43.69 82.17,43.69 83.44,44.96 82.55,49.53 80.01,49.53 82.55,46.99 85.09,46.86 80.01,46.99 80.9,44.96 78.74,52.07 76.58,52.07 76.58,49.53 83.57,64.39 83.57,60.83 85.09,54.61 74.68,63.5 71.76,60.71 75.06,60.58 73.79,61.72 64.14,65.41 67.31,67.95 61.72,68.45 71.88,68.71 60.96,73.66 66.04,73.66 71.12,73.66 76.2,73.66 79.38,68.58 77.6,71.76 77.6,69.47 38.74,24.13 40.01,24.13 34.29,39.37 61.6,62.87 67.31,62.87 64.14,60.33 67.31,58.42 60.96,58.42 64.14,55.88 64.14,58.42 53.98,66.04 53.98,60.96 48.9,60.96 44.45,60.96 45.09,55.25 41.91,52.07 41.91,48.9 43.31,50.42 43.31,47.24 46.61,47.24 45.09,45.59 41.91,45.72 34.29,57.15 34.29,54.61 34.29,52.07 34.29,49.53 34.29,46.99 36.83,46.99 34.29,59.31 36.83,59.18 46.36,20.32
  pour Route3 (isolate 0.254): 86.23,74.93 0,74.93 0,0 86.36,0 86.36,3.81 arc-90 86.74,4.19 91.44,4.19 91.44,48.39 86.87,48.39 86.23,49.02
  pour Bottom (isolate 0.254): 85.73,47.75 92.33,47.75 92.2,11.43 86.74,11.43 86.74,14.35 83.19,14.35 83.19,12.07 80.65,12.07 80.65,3.81 85.73,3.81 85.73,0.64 79.38,0.64 79.38,74.3 85.73,74.3
  pour Bottom: 79.25,3.94 85.85,3.94 85.85,0.38 79.25,0.38
  pour Bottom (no thermals): 0.25,49.02 6.48,49.02 6.73,48.77 6.73,36.32 6.48,36.07 0.25,36.07
  pour Bottom (no thermals): 0.25,23.5 6.48,23.5 6.73,23.24 6.73,10.8 6.48,10.54 0.25,10.54
  pour L2-GND (isolate 0.305): 85.73,74.3 85.73,48.9 86.36,48.26 90.81,48.26 90.81,4.45 86.36,4.45 85.73,3.81 85.73,0.64 0.25,0.64 0.25,74.3
  pour Bottom (isolate 0.406, rank 2): 0.25,0.25 79.25,0.25 79.38,69.22 79.38,74.68 0.25,74.68
  pour Top (isolate 0.305, rank 5): 86.11,74.68 0.25,74.68 0.25,0.25 44.65,0.25 44.65,6.22 arc-90 45.29,6.86 57.73,6.86 arc-90 58.37,6.22 58.37,0.25 86.11,0.25 86.11,3.68 arc-90 86.74,4.32 91.69,4.32 91.69,48.26 86.87,48.26 arc-90 86.11,49.02
  pour Top (no thermals): 45.16,0.13 45.16,6.1 arc-90 45.42,6.35 57.61,6.35 arc-90 57.86,6.1 57.86,0.13
GND-ROM
  Bottom 0.203: J1.85 89.69,10.8 89.46,10.7 89.13,10.7 89,10.69 | U1.4 85.81,12.2 85.93,12.19 | U1.3 85.16,12.2 85.29,12.19 | 84.63,12.19 84.63,12.22 84.51,12.1 U1.2 U1.1 | 88.24,10.69 88.24,10.72 | J9.2 81.92,5.46 81.53,5.84 81.53,6.73 C27.2
  Bottom 0.254: 82.17,9.78 82.17,9.27 81.57,8.67 C27.2
  Bottom 0.406: 84.71,12.19 85.29,12.19 85.85,12.19 85.93,12.19 | 84.71,12.19 84.63,12.19 | 84.71,12.19 83.06,12.19 82.17,11.3 82.17,9.78
  Bottom 0.61: 89,10.69 88.24,10.69 86.59,10.69 85.85,11.43 85.85,12.19 | 88.24,10.72 87.88,10.72
IO_EN  (via drill 0.25)
  Top 0.203: Q1.1 82.93,7.81 82.93,7.87 83.37,8.32 R24.2 | 84.18,8.31 84.19,8.31 R24.2 | v87.12,5.21 87.12,6.35 85.17,8.31 84.2,8.31 R24.2 | R24.2 84.2,8.38
  Top 0.254: Q1.1 82.79,7.75 82.8,7.75 82.93,7.87 83.06,8
  Bottom 0.203: J1.99 90.89,5.21 v87.12,5.21
IO_EN#  (via drill 0.3, 0.38)
  Top 0.254: R17.1 77.03,47.31 77.34,46.99 v77.34,44.83 76.93,44.42 U3.22 | U4.22 76.93,36.55 v77.34,36.96 | U5.22 76.81,28.42 v77.34,28.96 | U7.22 76.81,20.29 v77.34,20.83
  Top 0.305: Q1.3 80.65,8.78 79.76,9.65 v79.76,11.18
  Bottom 0.254: 77.34,44.96 v77.34,44.83 v77.34,36.96 v77.34,28.96
  Bottom 0.305: v79.76,11.18 79.76,12.7 77.34,14.86 v77.34,20.83 v77.34,28.96
LO
  Bottom 0.406: 23.88,36.7 C7.1 | 23.88,36.7 C5.1 | 23.88,36.7 18.16,36.7 12.45,42.42 C21.2
LO_IN  (via drill 0.38)
  Top 0.305: U9.E2 26.67,28.58 v24.77,28.58
  Bottom 0.406: v24.77,28.58 24,28.58 24,28.61 C18.1 C17.2
MIX_EN  (via drill 0.25)
  Top 0.203: U9.E4 v30.48,29.85 | v31.12,39.62 31.12,42.29 32.39,43.56 37.08,43.56 38.35,44.83 38.35,62.23 38.1,62.48 22.73,62.48 22.23,62.99 22.23,66.93 21.84,67.31 19.94,67.31 19.81,67.44 J8.2
  L2-GND 0.203: v30.48,29.85 31.12,30.48 31.12,34.54 30.48,35.18 30.48,35.94 31.12,36.58 v31.12,39.62
MODE  (via drill 0.25)
  Top 0.203: U9.J13 v41.91,34.93 | v40.64,41.91 40.64,44.07 40.26,44.45 40.26,63.75 41.28,64.77 41.28,67.31 | 40.26,67.31 J4.3 41.28,67.31 | 42.29,67.31 J4.4 41.28,67.31
  L2-GND 0.203: v41.91,34.93 41.91,41.15 41.15,41.91 v40.64,41.91
MUX  (via drill 0.25)
  Top 0.152: U9.D13 v41.91,28.58
  Bottom 0.254: R39.2 41.91,29.34 v41.91,28.58 | R39.2 41.91,29.46 | R39.2 SJ4.2
MUXCLK
  Bottom 0.254: SJ4.3 43.18,29.97 43.82,29.34 R10.2
N$1
  Bottom 0.305: 47.75,32 R2.2 47.75,32.77 47.63,32.89 C6.1 47.66,33.02 47.63,33.02 47.61,33.01 | U8.5 46.34,33.01 | 45.47,31.88 45.34,31.77 U2.5 | 46.36,33.01 46.36,33.02 45.85,33.53 45.85,35.81 45.72,35.94 C3.1 45.85,35.94 45.34,36.45 45.34,37.08 44.82,37.6 L1.1
  Bottom 0.406: 47.61,33.01 U8.5 46.36,33.01 | 46.34,33.01 45.85,32.51 45.85,32.26 45.47,31.88
N$2
  Bottom 0.254: U2.2 47.63,31.12 47.75,30.99 | 47.75,30.99 R2.1 | R1.2 47.81,31.05 47.75,30.99 | R1.2 49.02,31.12 | R1.2 C2.2
N$3
  Bottom 0.254: J11.1 2.92,17.02
  Bottom 0.406: J11.1 C22.1
N$4
  Bottom 0.305: J6.1 2.79,42.42
  Bottom 0.406: J6.1 C21.1
N$5
  Top 0.152: U6.11 78.63,63.74 SJ1.2 77.85,63.75 77.79,63.69 R19.2
N$6
  Top 0.203: U6.12 78.11,62.39 78.11,62.23 77.22,62.23 76.84,61.85 76.33,61.85 R22.2 R20.1 76.33,60.07
N$10
  Top 0.152: U6.8 80.13,63.74 SJ2.2 R30.2
N$11
  Bottom 0.254: R36.2 40.83,70.36 40.77,70.36 40.28,69.87 J4.1 40.28,69.34 39.37,69.34 38.99,68.96 R37.1
N$12
  Bottom 0.254: R15.1 47.75,34.04 47.48,34.31 U8.4
N$14
  Top 0.203: U9.L1 25.65,36.45 10.29,36.45 8.26,34.42 8.26,32.26 7.11,31.12 R3.3
N$15
  Top 0.152: C11.2 75.18,59.56 75.31,59.69 77.09,59.69
  Top 0.203: U6.1 77.27,59.51 77.09,59.69
N$16
  Top 0.152: C13.2 83.57,59.56 83.44,59.69 81.66,59.69
  Top 0.203: U6.6 81.48,59.51 81.66,59.69
N$18
  Top 0.203: U6.7 80.63,62.25 80.65,62.23 81.53,62.23 81.92,61.85 82.42,61.85 R23.2 R21.1
N$19
  Top 0.203: U9.K1 25.65,35.94 10.54,35.94 8.89,34.29 8.89,31.37 7.62,30.23 6.22,30.23 5.33,31.12 R3.1
N$20
  Top 0.203: U9.C1 25.65,26.29 7.24,26.29 R4.3
N$21
  Top 0.203: U9.B1 25.65,25.78 8.51,25.78 7.87,25.15 6.48,25.15 5.59,26.04 R4.1
N$22  (via drill 0.3)
  Top 0.254: U3.2 73.93,45.21 v73.15,45.21 71.63,45.21 71.37,45.47 71.37,46.99 71.63,47.24 R18.1 | U5.2 73.93,29.21 v73.15,29.21 | U4.2 73.93,37.34 v73.15,37.34 | U7.2 73.93,21.08 v73.15,21.08
  Bottom 0.254: v73.15,45.21 73.15,39.12 73.28,38.99 73.28,37.85 73.15,37.72 v73.15,37.34 v73.15,29.21 v73.15,21.08
N$23
  Bottom 0.254: R3.2 R6.2
N$26
  Bottom 0.254: R4.2 R7.1
N$32
  Top 0.254: U4.14 83.07,32.5 85.6,29.97 J1.46 | J1.46 | J1.46 91.06,30.1
N$33
  Top 0.254: U4.15 83.41,33.05 85.73,30.73 90.93,30.73 90.93,30.74 J1.44
N$35
  Top 0.254: U4.16 83.93,33.55 85.09,32.39 90.55,32.39 90.57,32.37 J1.40
N$37
  Top 0.254: U4.17 84.44,34.05 85.34,33.15 90.42,33.15 90.55,33.27 90.66,33.17 J1.38
N$38
  Top 0.254: U4.18 84.46,34.55 84.71,34.8 90.68,34.8 90.81,34.67 90.9,34.77 J1.34
N$39
  Top 0.254: U4.19 83.56,35.05 84.07,35.56 90.42,35.56 90.43,35.57 J1.32
N$40
  Top 0.254: U4.20 82.79,35.55 84.46,37.21 90.68,37.21 90.72,37.17 J1.28
N$41
  Top 0.254: U4.21 82.15,36.05 84.07,37.97 90.68,37.97 90.69,37.97 J1.26
N$42
  Top 0.254: U3.14 84.85,40.37 85.6,39.62 91.19,39.62 91.13,39.57 J1.22
N$43
  Top 0.254: U3.15 85.57,40.92 86.11,40.39 90.81,40.39 90.83,40.37 J1.20
N$45
  Top 0.254: U3.16 85.49,41.42 86.11,42.04 90.81,42.04 90.93,41.91 | 90.93,41.91 | 90.93,41.91 J1.16
N$46
  Top 0.254: U3.17 84.34,41.92 85.22,42.8 90.68,42.8 90.71,42.77 J1.14
N$47
  Top 0.254: U3.18 83.32,42.42 85.34,44.45 91.31,44.45 91.23,44.37 J1.10
N$48
  Top 0.254: U3.19 82.55,42.92 84.84,45.21 90.81,45.21 90.85,45.17 J1.8
N$50
  Top 0.152: 78.11,28.55 SJ3.2 78.11,28.35
  Top 0.254: J1.50 82.76,28.37 82.68,28.45 SJ3.2
N$61
  Bottom 0.254: R37.2 38.99,65.66 39.37,65.28 40.26,65.28 | R42.2 40.77,64.2 40.77,64.39 40.26,64.9 40.26,65.28 | 40.26,65.28 J4.5
N$76
  Top 0.254: J1.100 88.82,5.17 87.76,6.22 87.76,6.86 86.49,8.13 86.49,9.14 84.33,11.3 84.33,12.32 80.39,16.26 75.43,16.26 U7.14
N$77
  Top 0.254: J1.98 88.78,5.97 88.27,6.48 88.27,7.24 87,8.51 87,9.4 84.84,11.56 84.84,12.57 80.62,16.79 U7.15
N$78
  Top 0.254: J1.94 88.7,7.57 87.5,8.76 87.5,9.65 85.34,11.81 85.34,12.95 81.03,17.27 76.45,17.27 76.45,17.29 U7.16
N$79
  Top 0.254: J1.92 88.66,8.37 88.01,9.02 88.01,9.91 85.85,12.07 85.85,13.21 81.28,17.78 76.58,17.78 76.58,17.79 U7.17
N$80
  Top 0.254: J1.88 88.71,9.97 86.36,12.32 86.36,13.46 81.53,18.29 76.58,18.29 U7.18
N$89
  Bottom 0.203: 84.51,7.48 U1.7 | 84.51,7.48 84.51,8.33 84.33,8.51 82.55,8.51 82.42,8.64 R43.1 | 84.46,5.46 J9.1 84.51,5.59 84.51,7.48
N$96
  Top 0.254: J1.76 88.11,14.77 82.8,20.07 82.8,23.5 81.92,24.38 75.43,24.38 U5.14
N$97
  Top 0.254: 76.46,27.41 76.3,27.41 | U5.20 76.46,27.41 | J1.52 78.62,27.57 78.46,27.41 76.46,27.41
N$98
  Top 0.254: J1.74 88.07,15.57 83.31,20.32 83.31,24.13 82.55,24.89 76.58,24.89 76.58,24.92 U5.15
N$99
  Top 0.254: J1.70 87.23,17.17 83.82,20.57 83.82,24.38 82.8,25.4 76.45,25.4 76.45,25.42 U5.16
N$100
  Top 0.254: J1.68 87.19,17.97 84.33,20.83 84.33,24.77 83.19,25.91 76.45,25.91 76.45,25.92 U5.17
N$101
  Top 0.254: J1.64 86.48,19.57 84.84,21.21 84.84,25.15 83.57,26.42 76.58,26.42 U5.18
N$103
  Top 0.254: J1.62 86.57,20.37 85.34,21.59 85.34,25.53 83.95,26.92 76.33,26.92 U5.19
N$104
  Top 0.254: J1.86 88.68,10.77 87,12.45 87,13.59 81.79,18.8 76.58,18.8 76.58,18.79 U7.19
N$105
  Top 0.254: J1.82 88.6,12.37 87.5,13.46 87.5,13.84 82.04,19.3 76.58,19.3 76.58,19.29 U7.20
N$106
  Top 0.254: J1.80 88.56,13.17 88.14,13.59 88.14,13.97 82.3,19.81 76.58,19.81 76.58,19.79 U7.21
N$111  (via drill 0.25)
  Top 0.152: SJ3.3 78.11,28.85
  Top 0.203: SJ3.3 78.11,30.48 76.84,31.75 v68.83,31.75
  Bottom 0.406: R15.2 66.55,34.04 v68.83,31.75
N$116
  Top 0.152: SJ3.1 78.11,28.04
  Top 0.254: U5.21 78.11,27.92 SJ3.1
OF
  Top 0.152: U9.H12 OF.1
OVDD  (via drill 0.38)
  Top 0.406: U9.J17 47.37,34.29 v48.13,35.05 | v47.12,27.94 U9.D17
  Top 0.61: J2.3 R16.1
  L2-GND 0.406: v47.12,27.94 47.12,34.04 v48.13,35.05
  Bottom 0.406: v48.13,35.05 49.78,35.05 52.32,37.59 52.32,40.64 52.58,40.89 52.58,53.21 | 47.24,27.94 v47.12,27.94 46.05,27.94 C23.1
  Bottom 0.61: J2.3 69.72,53.98 69.34,53.59 52.96,53.59 52.58,53.21
PWR-ON  (via drill 0.25)
  Top 0.203: R29.1 81.79,10.98 81.79,7.24 82.17,6.86 85.98,6.86 86.49,6.35 v86.49,5.84
  Bottom 0.203: J1.97 90.81,5.84 v86.49,5.84
RF
  Bottom 0.406: 23.88,25.53 C17.1 | 23.88,25.53 C16.1 | 23.88,25.53 18.03,25.53 9.53,17.02 C22.2
RF_IN  (via drill 0.38)
  Top 0.305: U9.H3 27.94,33.66 v24.77,33.66
  Bottom 0.406: v24.77,33.66 23.88,33.66 C12.1 C7.2 23.88,34.8
SCL
  Bottom 0.203: 87.66,7.98 R25.1 87.63,7.99 87.63,9.53 | J1.87 88.07,9.97 87.63,9.53 | U1.6 85.16,8.58 86.11,9.53 87.63,9.53
SDA
  Bottom 0.127: 86.61,7.54 88.26,7.54
  Bottom 0.152: J1.91 90.91,8.38 89.1,8.38 88.26,7.54
  Bottom 0.203: 86.61,7.43 86.61,7.37 | R26.1 86.61,7.43 | 86.61,7.43 86.61,7.54 | U1.5 85.85,7.44 85.98,7.43 86.61,7.43
SENSE_I  (via drill 0.25)
  Top 0.203: 6.48,63.5 7.87,63.5 10.8,60.58 v37.72,60.58 | v40.64,28.58 U9.E13 | v41.91,41.91 41.91,44.07 41.02,44.96 41.02,59.31 41.66,59.94 v41.66,60.58
  Top 0.254: C4.1 3.81,61 3.81,61.72
  Top 0.305: 6.1,63.5 6.48,63.5
  Top 0.406: 5.59,63.5 6.1,63.5 | 3.81,61.72 TP1.1
  Top 0.61: TP1.1 5.59,63.5
  L2-GND 0.203: v40.64,28.58 42.55,30.48 42.55,41.28 v41.91,41.91 | v37.72,60.58 v41.66,60.58
  Bottom 0.203: R33.2 40.45,29.02 40.64,28.83 v40.64,28.58
SENSE_Q  (via drill 0.25)
  Top 0.203: 6.35,57.15 7.87,57.15 10.8,60.07 v37.21,60.07 | v41.02,41.15 41.02,41.4 41.28,41.66 41.28,44.07 40.64,44.7 40.64,59.69 v41.02,60.07
  Top 0.254: C1.1 3.81,59.65 3.81,58.93 | v40.64,32.39 U9.H13
  Top 0.305: 5.97,57.15 6.35,57.15
  Top 0.406: 5.59,57.15 5.97,57.15 | TP12.1 3.81,58.93
  Top 0.61: TP12.1 5.59,57.15
  L2-GND 0.203: v40.64,32.39 U9.H13 41.28,40.89 v41.02,41.15 | v37.21,60.07 v41.02,60.07
  Bottom 0.203: R34.2 39.88,34.54 39.88,33.15 v40.64,32.39
SHDNI  (via drill 0.25)
  Top 0.203: U9.D12 v39.37,28.58 | v38.74,41.02 38.74,43.56 39.5,44.32 39.5,63.63 39.24,63.88 33.91,63.88 33.66,64.14 33.66,67.06 33.4,67.31 J3.3
  L2-GND 0.203: v39.37,28.58 38.74,29.21 38.74,29.72 38.61,29.85 38.61,30.1 38.74,30.35 38.74,31.88 38.61,32 38.61,32.39 38.74,32.51 v38.74,41.02
SHDNQ  (via drill 0.25)
  Top 0.203: v39.37,33.66 U9.J12 | v40.01,41.15 40.01,44.07 39.88,44.2 39.88,63.88 39.5,64.26 36.07,64.26 35.69,64.64 35.69,67.06 35.43,67.31 J3.4
  L2-GND 0.203: v39.37,33.66 U9.J12 v40.01,41.15
VCC3  (via drill 0.3)
  Top 0.305: v36.83,36.2 U9.K9 | v39.37,36.2 U9.K12 | U9.C9 v36.83,26.04 | v39.37,26.04 U9.C12
  Bottom 0.305: C24.1 35.94,35.24 35.94,35.31
  Bottom 0.508: 38.48,36.32 37.85,36.32 37.72,36.2 v36.83,36.2 36.32,36.2 35.94,35.81 35.94,35.31 35.94,26.92 v36.83,26.04 37.47,26.04 37.72,26.29 38.35,26.29 38.61,26.04 v39.37,26.04 | 38.48,36.32 38.61,36.2 v39.37,36.2 | R32.1 40.4,39.23 40.26,39.37 40.18,39.42 38.52,39.42 38.47,39.37 R31.1 38.47,36.33 38.48,36.32
VIOA  (via drill 0.3)
  Top 0.254: U5.1 74.43,29.71 73.91,30.23 C36.1 73.91,30.26 v73.91,31.12 | U4.1 74.43,37.84 73.91,38.35 C35.1 73.91,38.39 v73.91,39.12 | U3.1 74.43,45.72 73.91,46.23 | R17.2 76.13,47.56 76.07,47.63 74.17,47.63 v73.91,47.37 72.71,47.37 R18.2 | 73.91,46.23 C34.1 | 73.91,46.23 73.85,46.29 73.85,47.56 73.91,47.63 | 81.03,58.29 80.77,58.04 C8.1 80.71,57.98 80.13,58.56 U6.5 | U7.1 74.43,21.59 73.91,22.1 C32.1 73.91,22.13 v73.91,22.99 | 82.42,57.66 82.42,58.55 | 82.42,58.55 R21.2 | C13.1 83.4,58.55 82.42,58.55
  Top 0.406: 80.71,57.98 80.96,57.98 | v73.91,47.37 73.91,47.63 73.91,53.09 74.04,53.21 74.04,53.72 | 74.04,53.72 74.3,54.1 81.53,54.1 82.68,55.25 82.68,57.02 | 81.03,58.29 81.28,58.04 81.28,57.66 82.42,57.66 82.55,57.66 82.68,57.53 82.68,57.02 | 82.68,57.02 82.68,57.15 | 74.04,53.72 R16.2 74.42,53.72
  Bottom 0.406: v73.91,47.37 v73.91,39.12 v73.91,31.12 v73.91,22.99
VIOB  (via drill 0.3)
  Top 0.254: C30.1 75.57,30.23 | U5.23 75.43,30.23 75.44,30.35 | C30.1 75.44,30.39 v75.44,31.12 | C30.1 75.44,30.35 | U5.24 74.93,29.84 75.44,30.35 | C29.1 75.57,38.35 | U4.23 75.43,38.35 C29.1 | C29.1 75.44,38.35 v75.44,39.12 | U4.24 74.93,37.97 75.31,38.35 C29.1 | U3.23 75.43,46.22 75.44,46.23 C28.1 75.31,46.23 | U3.24 74.93,45.84 75.31,46.23 | 75.31,46.23 75.57,46.23 75.44,46.36 v75.44,46.99 | U6.2 78.63,58.03 78.74,57.91 C9.1 78.74,58.04 79.13,58.42 U6.3 | C11.1 75.4,58.58 75.57,58.42 76.2,58.42 76.71,57.91 C10.1 76.64,57.98 76.58,57.91 76.33,58.17 R20.2 | C31.1 75.44,22.13 v75.44,22.99 | C31.1 75.44,22.1 75.44,20.85 U7.23 | C31.1 75.31,22.1 74.93,21.71 U7.24
  Top 0.61: 76.58,57.79 76.58,57.85 C10.1 | C10.1 76.84,57.85 76.84,57.79 78.38,57.79 78.63,58.03 | J2.1 72.77,59.06 74.17,57.66 76.45,57.66 76.58,57.98 C10.1
  Bottom 0.406: v75.44,46.99 v75.44,39.12 v75.44,31.12 v75.44,22.99
  Bottom 0.61: v75.44,46.99 75.44,56.39 72.77,59.06 J2.1
VROM  (via drill 0.25)
  Bottom 0.152: 83.87,7.37 U1.8
  Bottom 0.203: J1.93 90.04,7.57 88.88,7.57 88.39,7.11 88.14,7.11 88.16,7.14 87.88,7.14 87.66,6.91 | 87.66,6.91 R25.2 | 87.66,6.91 87.66,6.55 87.58,6.48 86.87,6.48 86.67,6.55 | 86.67,6.55 R26.2 86.5,6.54 86.41,6.45 86.26,6.35 86.11,6.35 85.85,6.1 85.85,4.83 85.47,4.45 83.69,4.45 83.52,4.62 v83.52,6.35 83.44,6.35 83.06,6.73 C27.1 82.51,7.66 82.42,7.75 R43.2 | 86.67,6.55 86.64,6.58 | 83.85,7.36 U1.8 83.95,7.32
  Bottom 0.254: v83.52,6.35 83.87,6.71 83.87,7.37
